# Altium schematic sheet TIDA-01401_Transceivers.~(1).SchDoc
size 431 x 279 mm; Date: Not shown in title block; ApprovedBy: Not shown in title block; CheckedBy: Not shown in title block; Author: Not shown in title block; CompanyName: Not shown in title block; Engineer: Not shown in title block; Organization: Not shown in title block; Address1: Not shown in title block; Address2: Not shown in title block; Address3: Not shown in title block; Address4: Not shown in title block; DocumentNumber: 1; Revision: Use project parameter SCH_Rev; SheetNumber: 2; SheetTotal: 3; PageSetup: Record=PageOptions¦CenterHorizontal=True¦CenterVertical=True¦PrintScale=0.91¦XCorrection=1.00¦YCorrection=1.00¦PrintKind=0¦BorderSize=5000000¦LeftOffset=0¦BottomOffset=0¦Orientation=2¦PaperLength=1000¦PaperWidth=1000¦Scale=100¦PaperSource=15¦PrintQuality=-3¦MediaType=1¦DitherType=10¦PrintScaleMode=1¦PaperKind=A4¦PaperIndex=9
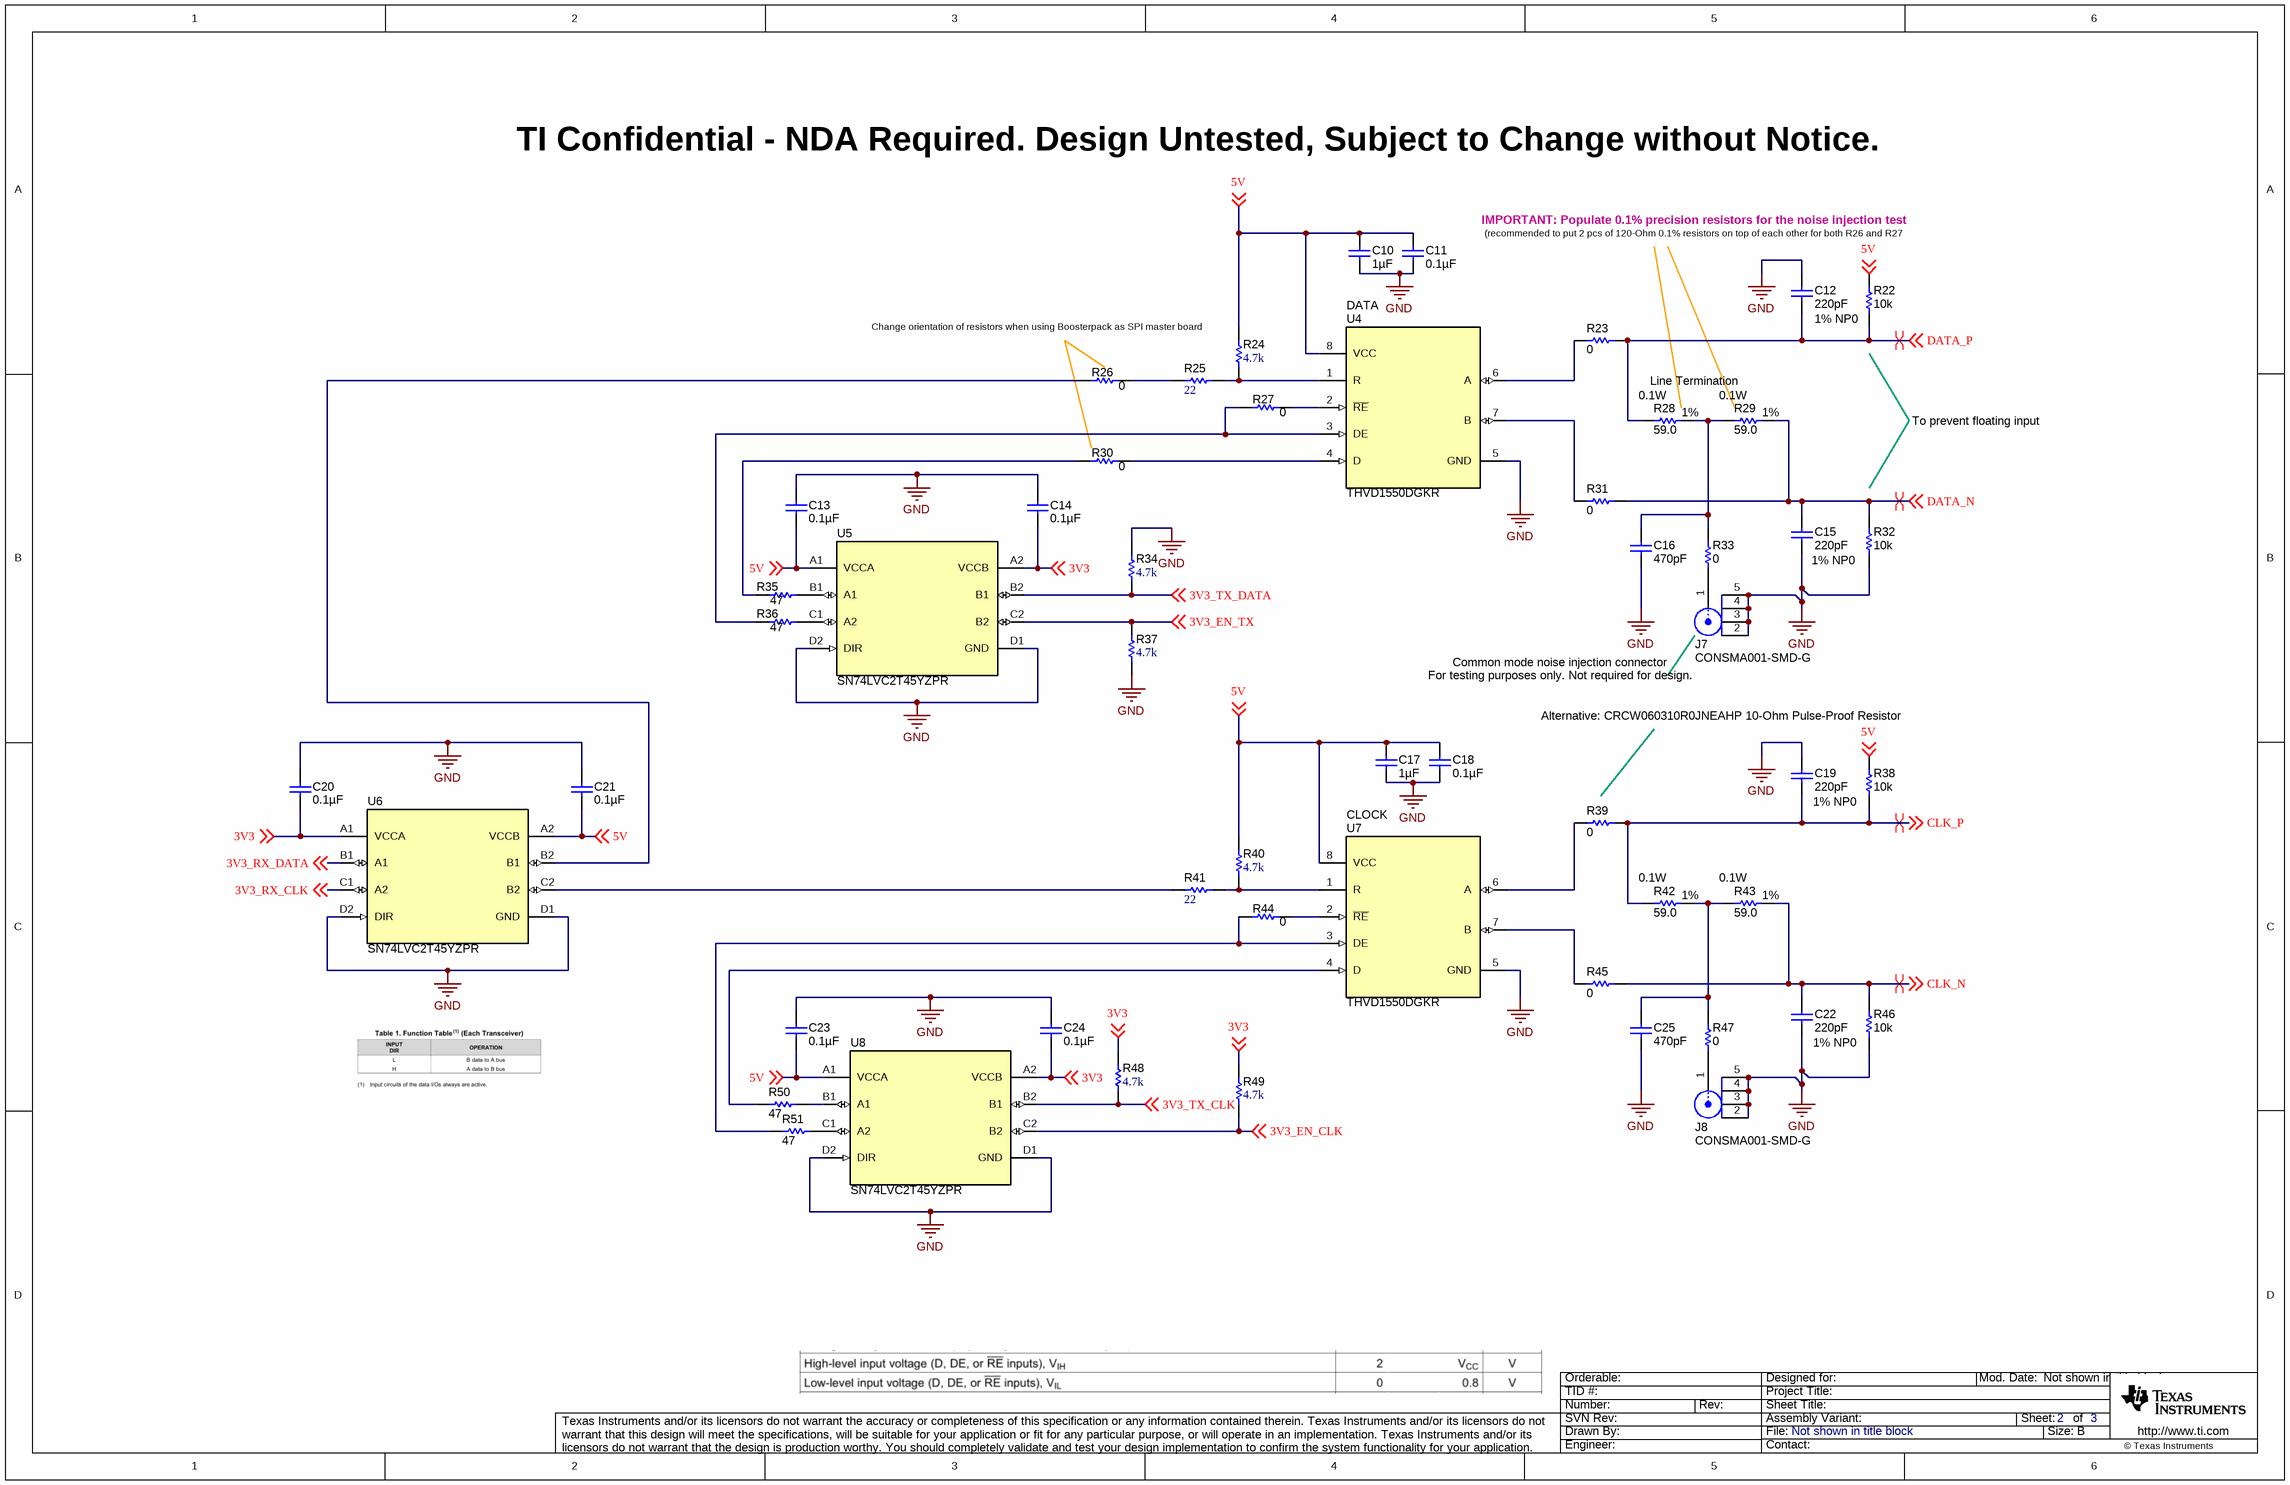
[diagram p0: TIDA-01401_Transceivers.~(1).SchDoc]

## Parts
C10  ValueDisplayed: 1µF  [0402S]  (hidden comment: GRM155R61A105KE15D)
C11  ValueDisplayed: 0.1µF  [0402S]  (hidden comment: 885012205037)
C12  ValueDisplayed: 220pF  [0603S]  (hidden comment: 06035A221FAT2A)
C13  ValueDisplayed: 0.1µF  [0402S]  (hidden comment: 885012205037)
C14  ValueDisplayed: 0.1µF  [0402S]  (hidden comment: 885012205037)
C15  ValueDisplayed: 220pF  [0603S]  (hidden comment: 06035A221FAT2A)
C16  ValueDisplayed: 470pF  [0603S]  (hidden comment: 885012206081)
C17  ValueDisplayed: 1µF  [0402S]  (hidden comment: GRM155R61A105KE15D)
C18  ValueDisplayed: 0.1µF  [0402S]  (hidden comment: 885012205037)
C19  ValueDisplayed: 220pF  [0603S]  (hidden comment: 06035A221FAT2A)
C20  ValueDisplayed: 0.1µF  [0402S]  (hidden comment: 885012205037)
C21  ValueDisplayed: 0.1µF  [0402S]  (hidden comment: 885012205037)
C22  ValueDisplayed: 220pF  [0603S]  (hidden comment: 06035A221FAT2A)
C23  ValueDisplayed: 0.1µF  [0402S]  (hidden comment: 885012205037)
C24  ValueDisplayed: 0.1µF  [0402S]  (hidden comment: 885012205037)
C25  ValueDisplayed: 470pF  [0603S]  (hidden comment: 885012206081)
J7  CONSMA001-SMD-G  [Linx_CONSMA001-SMD-G]
J8  CONSMA001-SMD-G  [Linx_CONSMA001-SMD-G]
R22  ValueDisplayed: 10k  [0603S]  (hidden comment: CRCW060310K0JNEA)
R23  ValueDisplayed: 0  [0603S]  (hidden comment: CRCW06030000Z0EA)
R24  ValueDisplayed: 4.7k  [0402S]  (hidden comment: CRCW04024K70JNED)
R25  ValueDisplayed: 22  [0402S]  (hidden comment: CRCW040222R0JNED)
R26  ValueDisplayed: 0  [0402S]  (hidden comment: CRCW04020000Z0ED)
R27  ValueDisplayed: 0  [0402S]  (hidden comment: CRCW04020000Z0ED)
R28  ValueDisplayed: 59.0  Value1: 1%  Value2: 0.1W  [0603S]  (hidden comment: RC0603FR-0759RL)
R29  ValueDisplayed: 59.0  Value1: 1%  Value2: 0.1W  [0603S]  (hidden comment: RC0603FR-0759RL)
R30  ValueDisplayed: 0  [0402S]  (hidden comment: CRCW04020000Z0ED)
R31  ValueDisplayed: 0  [0603S]  (hidden comment: CRCW06030000Z0EA)
R32  ValueDisplayed: 10k  [0603S]  (hidden comment: CRCW060310K0JNEA)
R33  ValueDisplayed: 0  [0402S]  (hidden comment: CRCW04020000Z0ED)
R34  ValueDisplayed: 4.7k  [0402S]  (hidden comment: CRCW04024K70JNED)
R35  ValueDisplayed: 47  [0402S]  (hidden comment: CRCW040247R0JNED)
R36  ValueDisplayed: 47  [0402S]  (hidden comment: CRCW040247R0JNED)
R37  ValueDisplayed: 4.7k  [0402S]  (hidden comment: CRCW04024K70JNED)
R38  ValueDisplayed: 10k  [0603S]  (hidden comment: CRCW060310K0JNEA)
R39  ValueDisplayed: 0  [0603S]  (hidden comment: CRCW06030000Z0EA)
R40  ValueDisplayed: 4.7k  [0402S]  (hidden comment: CRCW04024K70JNED)
R41  ValueDisplayed: 22  [0402S]  (hidden comment: CRCW040222R0JNED)
R42  ValueDisplayed: 59.0  Value1: 1%  Value2: 0.1W  [0603S]  (hidden comment: RC0603FR-0759RL)
R43  ValueDisplayed: 59.0  Value1: 1%  Value2: 0.1W  [0603S]  (hidden comment: RC0603FR-0759RL)
R44  ValueDisplayed: 0  [0402S]  (hidden comment: CRCW04020000Z0ED)
R45  ValueDisplayed: 0  [0603S]  (hidden comment: CRCW06030000Z0EA)
R46  ValueDisplayed: 10k  [0603S]  (hidden comment: CRCW060310K0JNEA)
R47  ValueDisplayed: 0  [0402S]  (hidden comment: CRCW04020000Z0ED)
R48  ValueDisplayed: 4.7k  [0402S]  (hidden comment: CRCW04024K70JNED)
R49  ValueDisplayed: 4.7k  [0402]  (hidden comment: CRCW04024K70JNED)
R50  ValueDisplayed: 47  [0402S]  (hidden comment: CRCW040247R0JNED)
R51  ValueDisplayed: 47  [0402S]  (hidden comment: CRCW040247R0JNED)
U4  THVD1550DGKR  [DGK0008A_N]
U5  SN74LVC2T45YZPR  [YZP0008ADAD]
U6  SN74LVC2T45YZPR  [YZP0008ADAD]
U7  THVD1550DGKR  [DGK0008A_N]
U8  SN74LVC2T45YZPR  [YZP0008ADAD]

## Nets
GND: C10.2 C11.2 C12.1 C13.1 C14.1 C15.2 C16.2 C17.2 C18.2 C19.1 C20.1 C21.1 C22.2 C23.1 C24.1 C25.2 J7.2 J7.3 J7.4 J7.5 J8.2 J8.3 J8.4 J8.5 R32.1 R34.2 R37.1 R46.1 U4.5(GND) U5.D1(GND) U5.D2(DIR) U6.D1(GND) U6.D2(DIR) U7.5(GND) U8.D1(GND) U8.D2(DIR)
3V3: C14.2 C20.2 C24.2 R48.2 R49.2 U5.A2(VCCB) U6.A1(VCCA) U8.A2(VCCB) ; off-sheet 3V3
3V3_EN_CLK: R49.1 U8.C2(B2) ; off-sheet 3V3_EN_CLK
3V3_EN_TX: R37.2 U5.C2(B2) ; off-sheet 3V3_EN_TX
3V3_RX_CLK: U6.C1(A2) ; off-sheet 3V3_RX_CLK
3V3_RX_DATA: U6.B1(A1) ; off-sheet 3V3_RX_DATA
3V3_TX_CLK: R48.1 U8.B2(B1) ; off-sheet 3V3_TX_CLK
3V3_TX_DATA: R34.1 U5.B2(B1) ; off-sheet 3V3_TX_DATA
5V: C10.1 C11.1 C13.2 C17.1 C18.1 C21.2 C23.2 R22.2 R24.2 R38.2 R40.2 U4.8(VCC) U5.A1(VCCA) U6.A2(VCCB) U7.8(VCC) U8.A1(VCCA) ; off-sheet 5V
CLK_N: C22.1 R43.2 R45.2 R46.2 ; off-sheet CLK_N
CLK_P: C19.2 R38.1 R39.2 R42.1 ; off-sheet CLK_P
DATA_N: C15.1 R29.2 R31.2 R32.2 ; off-sheet DATA_N
DATA_P: C12.2 R22.1 R23.2 R28.1 ; off-sheet DATA_P
NetC16_1: C16.1 R28.2 R29.1 R33.2
NetC25_1: C25.1 R42.2 R43.1 R47.2
NetJ7_1: J7.1 R33.1
NetJ8_1: J8.1 R47.1
NetR23_1: R23.1 U4.6(A)
NetR24_1: R24.1 R25.2 U4.1(R)
NetR25_1: R25.1 R26.2
NetR26_1: R26.1 U6.B2(B1)
NetR27_1: R27.1 R36.1 U4.3(DE)
NetR27_2: R27.2 U4.2(~{RE})
NetR30_1: R30.1 R35.1
NetR30_2: R30.2 U4.4(D)
NetR31_1: R31.1 U4.7(B)
NetR35_2: R35.2 U5.B1(A1)
NetR36_2: R36.2 U5.C1(A2)
NetR39_1: R39.1 U7.6(A)
NetR40_1: R40.1 R41.2 U7.1(R)
NetR41_1: R41.1 U6.C2(B2)
NetR44_1: R44.1 R51.1 U7.3(DE)
NetR44_2: R44.2 U7.2(~{RE})
NetR45_1: R45.1 U7.7(B)
NetR50_1: R50.1 U7.4(D)
NetR50_2: R50.2 U8.B1(A1)
NetR51_2: R51.2 U8.C1(A2)

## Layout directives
differential pair: CLK_N, CLK_P, DATA_N, DATA_P

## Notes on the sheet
- TI Confidential - NDA Required. Design Untested, Subject to Change without Notice.
- IMPORTANT: Populate 0.1% precision resistors for the noise injection test
- (recommended to put 2 pcs of 120-Ohm 0.1% resistors on top of each other for both R26 and R27
- (near R24) Change orientation of resistors when using Boosterpack as SPI master board
- DATA
- 1% NP0
- Line Termination
- To prevent floating input
- (near J7) Common mode noise injection connector
- (near J7) For testing purposes only. Not required for design.
- Alternative: CRCW060310R0JNEAHP 10-Ohm Pulse-Proof Resistor
- CLOCK

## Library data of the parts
C10 C17 = GRM155R61A105KE15D: CAP, CERM, 1 µF, 10 V, +/- 10%, X5R, 0402; Manufacturer: MuRata; Polarized: N; CompType: Capacitor; Value: 1uF; U/M: EA; Cap_F: 0.000001; Tolerance_%: 10; Value1: Unknown; Value2: 10V; TaMin_C: -55; TaMax_C: 85; Cap_Case: 0402; SizeArea_mm2: 0.5; SizeAreaWB_mm2: 3; SizeX_mm: 1; SizeZ_mm: 0.6; AEC Category: Q200
C11 C13 C14 C18 C20 C21 C23 C24 = 885012205037: CAP, CERM, 0.1 µF, 16 V, +/- 10%, X7R, 0402; Manufacturer: Wurth Elektronik; Polarized: N; CompType: Capacitor; Value: 0.1uF; U/M: EA; Cap_F: 0.0000001; Tolerance_%: 10; Value1: Unknown; VDC_V: 16; Value2: 16V; TaMin_C: -55; TaMax_C: 125; Cap_Case: 0402; SizeArea_mm2: 0.5; SizeAreaWB_mm2: 3; SizeX_mm: 1; SizeZ_mm: 0.6; AEC Category: Q200
C12 C15 C19 C22 = 06035A221FAT2A: CAP, CERM, 220 pF, 50 V, +/- 1%, C0G/NP0, 0603; Manufacturer: AVX; Polarized: N; CompType: Capacitor; Value: 220pF; U/M: EA; Cap_F: 0.00000000022; Tolerance_%: 1; ESR_ohm: 0.083; Value1: 0.083 ohm; VDC_V: 50; Value2: 50V; TaMin_C: -55; TaMax_C: 125; Cap_Case: 0603; SizeArea_mm2: 1.28; SizeAreaWB_mm2: 4.68; SizeX_mm: 1.6; SizeY_mm: 0.8; AEC Category: Q200
C16 C25 = 885012206081: CAP, CERM, 470 pF, 50 V, +/- 10%, X7R, 0603; Manufacturer: Wurth Elektronik; Polarized: N; CompType: Capacitor; Value: 470pF; U/M: EA; Cap_F: 0.00000000047; Tolerance_%: 10; Value1: Unknown; VDC_V: 50; Value2: 50V; TaMin_C: -55; TaMax_C: 125; Cap_Case: 0603; SizeArea_mm2: 1.28; SizeAreaWB_mm2: 4.68; SizeX_mm: 1.6; SizeY_mm: 0.8; SizeZ_mm: 1; AEC Category: Q200
J7 J8 = CONSMA001-SMD-G: Jack, SMA, PCB, Gold, SMT; Manufacturer: Linx Technologies; SymbolCreator: X0208326
R22 R32 R38 R46 = CRCW060310K0JNEA: RES, 10 k, 5%, 0.1 W, 0603; Manufacturer: Vishay-Dale; CompType: Resistor; Value: 10k; Res_ohm: 10000; Value_Code: 10k0; Tolerance_%: 5; Power_W: 0.1; Value2: 0.1W; VDC_V: 75; TempCo: 200 ppm/C; SizeArea_mm2: 1.28; SizeX_mm: 1.6; SizeY_mm: 0.8; SizeZ_mm: 1; EIA_Code: E24; U/M: EA; AEC Category: Q200
R23 R31 R39 R45 = CRCW06030000Z0EA: RES, 0, 5%, 0.1 W, 0603; Manufacturer: Vishay-Dale; CompType: Resistor; Value: 0; Value_Code: 0000; Tolerance_%: 5; Power_W: 0.1; Value2: 0.1W; VDC_V: 75; TempCo: 200 ppm/C; EIA_Code: E24; U/M: EA; SizeArea_mm2: 1.28; SizeX_mm: 1.6; SizeY_mm: 0.8; SizeZ_mm: 1; AEC Category: Q200
R24 R34 R37 R40 R48 R49 = CMP-0026938-4: RES, 4.7 k, 5%, 0.063 W, 0402; Manufacturer: Vishay-Dale; Power_W: 63mW; TempCo: 200 ppm/C; Value_Code: 4k70; U/M: EA; Value: 4.7k; EIA_Code: E24; SizeX_mm: 1; SizeY_mm: 0.5; SizeZ_mm: 0.6; Value2: 0.063W; CompType: Resistor; VDC_V: 50V; AEC Category: Q200
R25 R41 = CMP-0026880-2: RES, 22, 5%, 0.063 W, 0402; Manufacturer: Vishay-Dale; Power_W: 63mW; TempCo: 200 ppm/C; Value_Code: 22R0; U/M: EA; Value: 22; EIA_Code: E24; SizeX_mm: 1; SizeY_mm: 0.5; SizeZ_mm: 0.6; Value2: 0.063W; CompType: Resistor; VDC_V: 50V; AEC Category: Q200
R26 R27 R30 R33 R44 R47 = CRCW04020000Z0ED: RES, 0, 5%, 0.063 W, 0402; Manufacturer: Vishay-Dale; CompType: Resistor; Value: 0; Value_Code: 0000; Tolerance_%: 5; Power_W: 0.063; Value2: 0.063W; VDC_V: 50; TempCo: 200 ppm/C; SizeArea_mm2: 0.5; SizeX_mm: 1; SizeZ_mm: 0.6; EIA_Code: E24; U/M: EA; AEC Category: Q200
R28 R29 R42 R43 = RC0603FR-0759RL: RES, 59.0, 1%, 0.1 W, 0603; Manufacturer: Yageo America; CompType: Resistor; Value: 59.0; Res_ohm: 59; Value_Code: 59R0; Tolerance_%: 1; Power_W: 0.1; VDC_V: 150; TempCo: 200 ppm/C; SizeArea_mm2: 1.28; SizeX_mm: 1.6; SizeY_mm: 0.8; EIA_Code: E96; U/M: EA; AEC Category: Q200
R35 R36 R50 R51 = CRCW040247R0JNED: RES, 47, 5%, 0.063 W, 0402; Manufacturer: Vishay-Dale; CompType: Resistor; Value: 47; Value_Code: 47R0; Tolerance_%: 5; Power_W: 0.063; Value2: 0.063W; VDC_V: 50; TempCo: 200 ppm/C; SizeArea_mm2: 0.5; SizeX_mm: 1; SizeZ_mm: 0.6; EIA_Code: E24; U/M: EA; AEC Category: Q200
U4 U7 = CMP-0074780-2: 5-V RS-485 Transceivers With +/-16-kV IEC ESD Protection, DGK0008A (VSSOP-8); Manufacturer: Texas Instruments; SizeX_mm: 5.05; SizeY_mm: 3.1; CompType: IC; SizeZ_mm: 1.1; SizeArea_mm2: 15.655; SizeAreaWB_mm2: 35.955; U/M: EA
U5 U6 U8 = SN74LVC2T45YZPR: 2-Bit Dual Supply Transceiver with Configurable Voltage-Level Shifting and 3-State Outputs, YZP0008ADAD (DSBGA-8); Manufacturer: Texas Instruments; SymbolCreator: a0411947; SizeArea_mm2: 2.8125; SizeAreaWB_mm2: 7.3125; SizeX_mm: 1.25; SizeY_mm: 2.25; SizeZ_mm: 0.5; CompType: IC; U/M: EA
